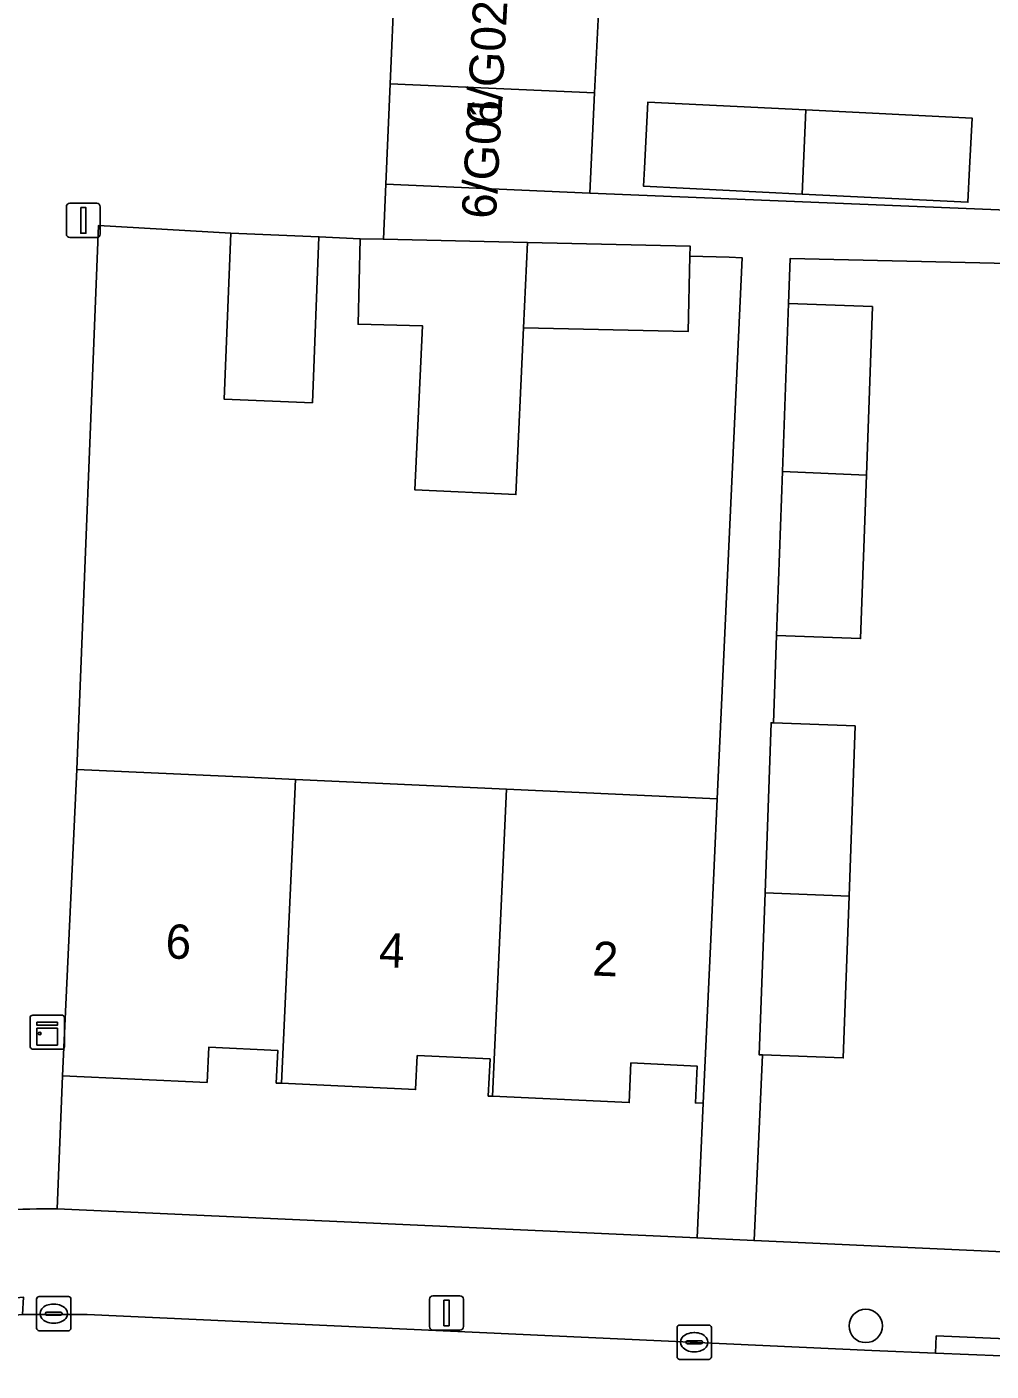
# Model space of a CAD drawing. Extents: x 160077 to 160948, y 386481 to 387498.
# Drawn here: x 160567.01 to 160595.16, y 386715.4 to 386754.65 of the extents above; entities that cross this region are included whole.
import ezdxf

# ---------------------------------------------------------------- set-up
doc = ezdxf.new("R2010")
doc.units = 0
for name, color, linetype in [('IMGEO_Boom', 7, 'Continuous'), ('IMGEO_Erf', 7, 'Continuous'), ('IMGEO_Kast', 7, 'Continuous'), ('IMGEO_Kolk', 7, 'Continuous'), ('IMGEO_Lichtmast', 7, 'Continuous'), ('IMGEO_Muur', 7, 'Continuous'), ('IMGEO_Pand', 7, 'Continuous'), ('IMGEO_Pand_nummerreeks', 7, 'Continuous'), ('IMGEO_Rijbaan_lokaal_open', 7, 'Continuous'), ('IMGEO_Voetpad_open', 7, 'Continuous')]:
    doc.layers.add(name, color=color, linetype=linetype)

msp = doc.modelspace()

# ---------------------------------------------------------------- linework, layer by layer
at = {"layer": 'IMGEO_Boom'}
msp.add_circle((160591.502, 386716.716), 0.489, dxfattribs=at)
at = {"layer": 'IMGEO_Erf'}
for points in [[(160583.725, 386755.652), (160583.585, 386752.723), (160583.446, 386749.795), (160610.202, 386748.699), (160610.255, 386750), (160611.199, 386773.064)], [(160599.083, 386747.662), (160589.29, 386747.881), (160589.243, 386746.567), (160591.697, 386746.479), (160591.521, 386741.559), (160591.35, 386736.785), (160588.896, 386736.873), (160588.805, 386734.323), (160591.192, 386734.237), (160591.014, 386729.261), (160590.845, 386724.543), (160588.486, 386724.628), (160588.239, 386719.208), (160605.982, 386718.402)]]:
    msp.add_lwpolyline(points, dxfattribs=at)
for points in [[(160594.605, 386751.981), (160594.533, 386750.525), (160594.483, 386749.525), (160589.642, 386749.764), (160585.017, 386749.993), (160585.043, 386750.525), (160585.139, 386752.449), (160589.748, 386752.221)], [(160576.681, 386745.963), (160576.737, 386748.462), (160575.537, 386748.517), (160575.346, 386743.671), (160572.773, 386743.772), (160572.964, 386748.618), (160569.096, 386748.843), (160568.465, 386732.966), (160573.46, 386732.735), (160574.849, 386732.671), (160581.012, 386732.386), (160587.164, 386732.102), (160587.893, 386747.904), (160587.518, 386747.921), (160586.365, 386747.947), (160586.316, 386745.748), (160581.511, 386745.855), (160581.287, 386740.99), (160578.339, 386741.126), (160578.56, 386745.921)], [(160586.754, 386723.217), (160586.529, 386723.228), (160586.579, 386724.304), (160584.647, 386724.393), (160584.594, 386723.237), (160580.599, 386723.422), (160580.481, 386723.427), (160580.531, 386724.51), (160578.406, 386724.608), (160578.36, 386723.618), (160574.44, 386723.799), (160574.289, 386723.806), (160574.333, 386724.761), (160572.318, 386724.854), (160572.271, 386723.826), (160568.052, 386724.021), (160567.893, 386720.133), (160586.575, 386719.284)]]:
    msp.add_lwpolyline(points, close=True, dxfattribs=at)
at = {"layer": 'IMGEO_Kast'}
for p, q in [((160567.181, 386725.792), (160568.022, 386725.792)), ((160568.022, 386725.792), (160567.181, 386725.792)), ((160567.106, 386724.867), (160567.106, 386725.708)), ((160567.106, 386725.708), (160567.106, 386724.867)), ((160568.106, 386725.717), (160568.106, 386724.876)), ((160568.106, 386724.876), (160568.106, 386725.717)), ((160568.031, 386724.792), (160567.19, 386724.792)), ((160567.19, 386724.792), (160568.031, 386724.792))]:
    msp.add_line(p, q, dxfattribs=at)
for points in [[(160567.301, 386725.582), (160567.901, 386725.582), (160567.901, 386725.497), (160567.301, 386725.497), (160567.301, 386725.582)], [(160567.301, 386725.407), (160567.901, 386725.407), (160567.901, 386724.918), (160567.301, 386724.918), (160567.301, 386725.407)]]:
    msp.add_lwpolyline(points, dxfattribs=at)
msp.add_circle((160567.385, 386725.256), 0.0377, dxfattribs=at)
for centre, start, end in [((160567.184, 386725.714), 92.4484, 184.2845), ((160567.184, 386725.714), 92.4484, 184.2845), ((160568.028, 386725.714), 2.4484, 94.2845), ((160568.028, 386725.714), 2.4484, 94.2845), ((160567.184, 386724.87), 182.4484, 274.2845), ((160567.184, 386724.87), 182.4484, 274.2845), ((160568.028, 386724.87), 272.4484, 4.2845), ((160568.028, 386724.87), 272.4484, 4.2845)]:
    msp.add_arc(centre, 0.0779, start, end, dxfattribs=at)
at = {"layer": 'IMGEO_Kolk'}
for p, q in [((160567.369, 386717.575), (160568.221, 386717.575)), ((160567.294, 386716.649), (160567.294, 386717.501)), ((160567.782, 386717.355), (160567.807, 386717.355)), ((160568.295, 386717.501), (160568.295, 386716.649)), ((160567.553, 386717.069), (160567.553, 386717.081)), ((160567.991, 386717.032), (160567.593, 386717.032)), ((160567.596, 386717.118), (160567.994, 386717.118)), ((160567.805, 386716.795), (160567.78, 386716.795)), ((160568.037, 386717.081), (160568.037, 386717.069)), ((160586.068, 386716.74), (160586.92, 386716.74)), ((160568.221, 386716.575), (160567.369, 386716.575)), ((160585.993, 386715.814), (160585.993, 386716.666)), ((160586.481, 386716.52), (160586.506, 386716.52)), ((160586.994, 386716.666), (160586.994, 386715.814)), ((160586.252, 386716.234), (160586.252, 386716.246)), ((160586.69, 386716.197), (160586.292, 386716.197)), ((160586.295, 386716.283), (160586.693, 386716.283)), ((160586.504, 386715.96), (160586.479, 386715.96)), ((160586.736, 386716.246), (160586.736, 386716.234)), ((160586.92, 386715.74), (160586.068, 386715.74))]:
    msp.add_line(p, q, dxfattribs=at)
for points in [[(160567.369, 386717.575), (160568.221, 386717.575)], [(160567.294, 386716.649), (160567.294, 386717.501)], [(160568.295, 386717.501), (160568.295, 386716.649)], [(160586.068, 386716.74), (160586.92, 386716.74)], [(160568.221, 386716.575), (160567.369, 386716.575)], [(160585.993, 386715.814), (160585.993, 386716.666)], [(160586.994, 386716.666), (160586.994, 386715.814)], [(160586.92, 386715.74), (160586.068, 386715.74)]]:
    msp.add_lwpolyline(points, dxfattribs=at)
for centre, radius, start, end in [((160567.371, 386717.499), 0.0765, 91.552, 178.448), ((160567.371, 386717.499), 0.0765, 91.552, 178.448), ((160568.219, 386717.499), 0.0765, 1.552, 88.448), ((160568.219, 386717.499), 0.0765, 1.552, 88.448), ((160567.593, 386717.078), 0.0403, 85.8775, 175.7526), ((160567.59, 386717.068), 0.0366, 178.938, 274.7102), ((160567.994, 386717.075), 0.043, 264.8664, 352.4533), ((160567.998, 386717.08), 0.0386, 1.7309, 96.639), ((160586.07, 386716.664), 0.0765, 91.552, 178.448), ((160586.07, 386716.664), 0.0765, 91.552, 178.448), ((160586.918, 386716.664), 0.0765, 1.552, 88.448), ((160586.918, 386716.664), 0.0765, 1.552, 88.448), ((160567.371, 386716.651), 0.0765, 181.552, 268.448), ((160567.371, 386716.651), 0.0765, 181.552, 268.448), ((160568.219, 386716.651), 0.0765, 271.552, 358.448), ((160568.219, 386716.651), 0.0765, 271.552, 358.448), ((160586.292, 386716.243), 0.0403, 85.8775, 175.7526), ((160586.289, 386716.233), 0.0366, 178.938, 274.7102), ((160586.693, 386716.24), 0.043, 264.8664, 352.4533), ((160586.697, 386716.245), 0.0386, 1.7309, 96.639), ((160586.07, 386715.816), 0.0765, 181.552, 268.448), ((160586.07, 386715.816), 0.0765, 181.552, 268.448), ((160586.918, 386715.816), 0.0765, 271.552, 358.448), ((160586.918, 386715.816), 0.0765, 271.552, 358.448)]:
    msp.add_arc(centre, radius, start, end, dxfattribs=at)
for centre, major_axis, ratio, start_param, end_param in [((160567.781, 386717.075), (-0.387, 0.002), 0.722429, 4.712389, 7.853982), ((160567.806, 386717.075), (-0.39, 0.002), 0.717154, 1.570796, 4.712389), ((160586.48, 386716.24), (-0.387, 0.002), 0.722429, 4.712389, 7.853982), ((160586.505, 386716.24), (-0.39, 0.002), 0.717154, 1.570796, 4.712389)]:
    msp.add_ellipse(centre, major_axis=major_axis, ratio=ratio, start_param=start_param, end_param=end_param, dxfattribs=at)
at = {"layer": 'IMGEO_Lichtmast'}
for p, q in [((160568.162, 386748.594), (160568.162, 386749.394)), ((160568.162, 386749.394), (160568.162, 386748.594)), ((160568.262, 386749.494), (160569.052, 386749.494)), ((160569.052, 386749.494), (160568.262, 386749.494)), ((160569.152, 386749.394), (160569.152, 386748.594)), ((160569.152, 386748.594), (160569.152, 386749.394)), ((160569.052, 386748.494), (160568.262, 386748.494)), ((160568.262, 386748.494), (160569.052, 386748.494)), ((160578.864, 386717.594), (160579.654, 386717.594)), ((160579.654, 386717.594), (160578.864, 386717.594)), ((160578.764, 386716.694), (160578.764, 386717.494)), ((160578.764, 386717.494), (160578.764, 386716.694)), ((160579.754, 386717.494), (160579.754, 386716.694)), ((160579.754, 386716.694), (160579.754, 386717.494)), ((160579.654, 386716.594), (160578.864, 386716.594)), ((160578.864, 386716.594), (160579.654, 386716.594))]:
    msp.add_line(p, q, dxfattribs=at)
for points in [[(160568.582, 386749.369), (160568.732, 386749.369), (160568.732, 386748.619), (160568.582, 386748.619), (160568.582, 386749.369)], [(160579.184, 386717.469), (160579.334, 386717.469), (160579.334, 386716.719), (160579.184, 386716.719), (160579.184, 386717.469)]]:
    msp.add_lwpolyline(points, dxfattribs=at)
for centre, start, end in [((160568.262, 386749.394), 90, 180), ((160568.262, 386749.394), 90, 180), ((160569.052, 386749.394), 0, 90), ((160569.052, 386749.394), 360, 90), ((160568.262, 386748.594), 180, 270), ((160568.262, 386748.594), 180, 270), ((160569.052, 386748.594), 270, 0), ((160569.052, 386748.594), 270, 0), ((160578.864, 386717.494), 90, 180), ((160578.864, 386717.494), 90, 180), ((160579.654, 386717.494), 0, 90), ((160579.654, 386717.494), 360, 90), ((160578.864, 386716.694), 180, 270), ((160578.864, 386716.694), 180, 270), ((160579.654, 386716.694), 270, 0), ((160579.654, 386716.694), 270, 0)]:
    msp.add_arc(centre, 0.1, start, end, dxfattribs=at)
at = {"layer": 'IMGEO_Muur'}
msp.add_lwpolyline([(160572.964, 386748.618), (160569.096, 386748.843), (160568.465, 386732.966)], dxfattribs=at)
at = {"layer": 'IMGEO_Pand'}
for points in [[(160577.742, 386755.908), (160577.617, 386752.979), (160583.585, 386752.723), (160583.725, 386755.652)], [(160583.585, 386752.723), (160577.617, 386752.979), (160577.491, 386750.05), (160583.446, 386749.795)], [(160585.139, 386752.449), (160585.043, 386750.525), (160585.017, 386749.993), (160589.642, 386749.764), (160589.748, 386752.221)], [(160594.483, 386749.525), (160594.533, 386750.525), (160594.605, 386751.981), (160589.748, 386752.221), (160589.642, 386749.764)], [(160572.773, 386743.772), (160575.346, 386743.671), (160575.537, 386748.517), (160572.964, 386748.618)], [(160581.626, 386748.353), (160577.42, 386748.447), (160576.737, 386748.462), (160576.681, 386745.963), (160578.56, 386745.921), (160578.339, 386741.126), (160581.287, 386740.99), (160581.511, 386745.855)], [(160586.365, 386747.947), (160586.372, 386748.247), (160581.626, 386748.353), (160581.511, 386745.855), (160586.316, 386745.748)], [(160591.697, 386746.479), (160589.243, 386746.567), (160589.067, 386741.659), (160591.521, 386741.559)], [(160588.896, 386736.873), (160591.35, 386736.785), (160591.521, 386741.559), (160589.067, 386741.659)], [(160591.192, 386734.237), (160588.805, 386734.323), (160588.738, 386734.325), (160588.56, 386729.362), (160591.014, 386729.261)], [(160574.849, 386732.671), (160573.46, 386732.735), (160568.465, 386732.966), (160568.052, 386724.021), (160572.271, 386723.826), (160572.318, 386724.854), (160574.333, 386724.761), (160574.289, 386723.806), (160574.44, 386723.799)], [(160574.44, 386723.799), (160578.36, 386723.618), (160578.406, 386724.608), (160580.531, 386724.51), (160580.481, 386723.427), (160580.599, 386723.422), (160581.012, 386732.386), (160574.849, 386732.671)], [(160580.599, 386723.422), (160584.594, 386723.237), (160584.647, 386724.393), (160586.579, 386724.304), (160586.529, 386723.228), (160586.754, 386723.217), (160586.984, 386728.212), (160587.164, 386732.102), (160581.012, 386732.386)], [(160591.014, 386729.261), (160588.56, 386729.362), (160588.391, 386724.631), (160588.486, 386724.628), (160590.845, 386724.543)]]:
    msp.add_lwpolyline(points, close=True, dxfattribs=at)
at = {"layer": 'IMGEO_Rijbaan_lokaal_open'}
for points in [[(160567.893, 386720.133), (160568.052, 386724.021), (160568.465, 386732.966), (160569.096, 386748.843), (160572.964, 386748.618), (160575.537, 386748.517), (160576.737, 386748.462), (160577.42, 386748.447), (160577.491, 386750.05), (160577.617, 386752.979), (160577.742, 386755.908), (160577.868, 386758.838), (160577.993, 386761.767), (160578.119, 386764.696), (160575.043, 386764.828), (160572.049, 386764.956), (160569.056, 386765.084), (160566.063, 386765.213), (160563.142, 386765.338), (160563.373, 386770.74)], [(160606.312, 386715.396), (160597.395, 386715.765), (160593.538, 386715.924), (160591.679, 386716.001), (160568.768, 386717.052), (160566.885, 386717.053), (160565.023, 386716.883), (160563.183, 386716.548), (160562.052, 386716.255)]]:
    msp.add_lwpolyline(points, dxfattribs=at)
msp.add_arc((160567.612, 386698.961), 21.174, 89.2386, 106.5565, dxfattribs=at)
at = {"layer": 'IMGEO_Voetpad_open'}
for points in [[(160610.202, 386748.699), (160583.446, 386749.795), (160577.491, 386750.05), (160577.42, 386748.447), (160581.626, 386748.353), (160586.372, 386748.247), (160586.365, 386747.947), (160587.518, 386747.921), (160587.893, 386747.904), (160587.164, 386732.102), (160586.984, 386728.212), (160586.754, 386723.217), (160586.575, 386719.284), (160588.239, 386719.208), (160588.486, 386724.628), (160588.391, 386724.631), (160588.56, 386729.362), (160588.738, 386734.325), (160588.805, 386734.323), (160588.896, 386736.873), (160589.067, 386741.659), (160589.243, 386746.567), (160589.29, 386747.881), (160599.083, 386747.662)], [(160605.982, 386718.402), (160588.239, 386719.208), (160586.575, 386719.284), (160567.893, 386720.133)], [(160562.052, 386716.255), (160561.874, 386716.723), (160563.165, 386717.057), (160565.028, 386717.389), (160566.913, 386717.554), (160566.885, 386717.053), (160568.768, 386717.052), (160591.679, 386716.001), (160593.538, 386715.924), (160593.559, 386716.423), (160597.416, 386716.264), (160597.395, 386715.765), (160606.312, 386715.396)]]:
    msp.add_lwpolyline(points, dxfattribs=at)
msp.add_lwpolyline([(160593.538, 386715.924), (160597.395, 386715.765), (160597.416, 386716.264), (160593.559, 386716.423)], close=True, dxfattribs=at)
msp.add_arc((160567.612, 386698.961), 21.174, 89.2386, 106.5565, dxfattribs=at)

# ---------------------------------------------------------------- texts
at = {"layer": 'IMGEO_Pand_nummerreeks'}
for s, rotation, p in [('6/G02', 86.957, (160580.847, 386751.749)), ('6/G01', 86.957, (160580.702, 386749.025)), ('6', 357.6883, (160571.044, 386727.452)), ('4', 357.6883, (160577.278, 386727.2)), ('2', 357.6883, (160583.511, 386726.949))]:
    msp.add_text(s, height=1, rotation=rotation, dxfattribs=at).set_placement(p)

doc.saveas('drawing.dxf')
